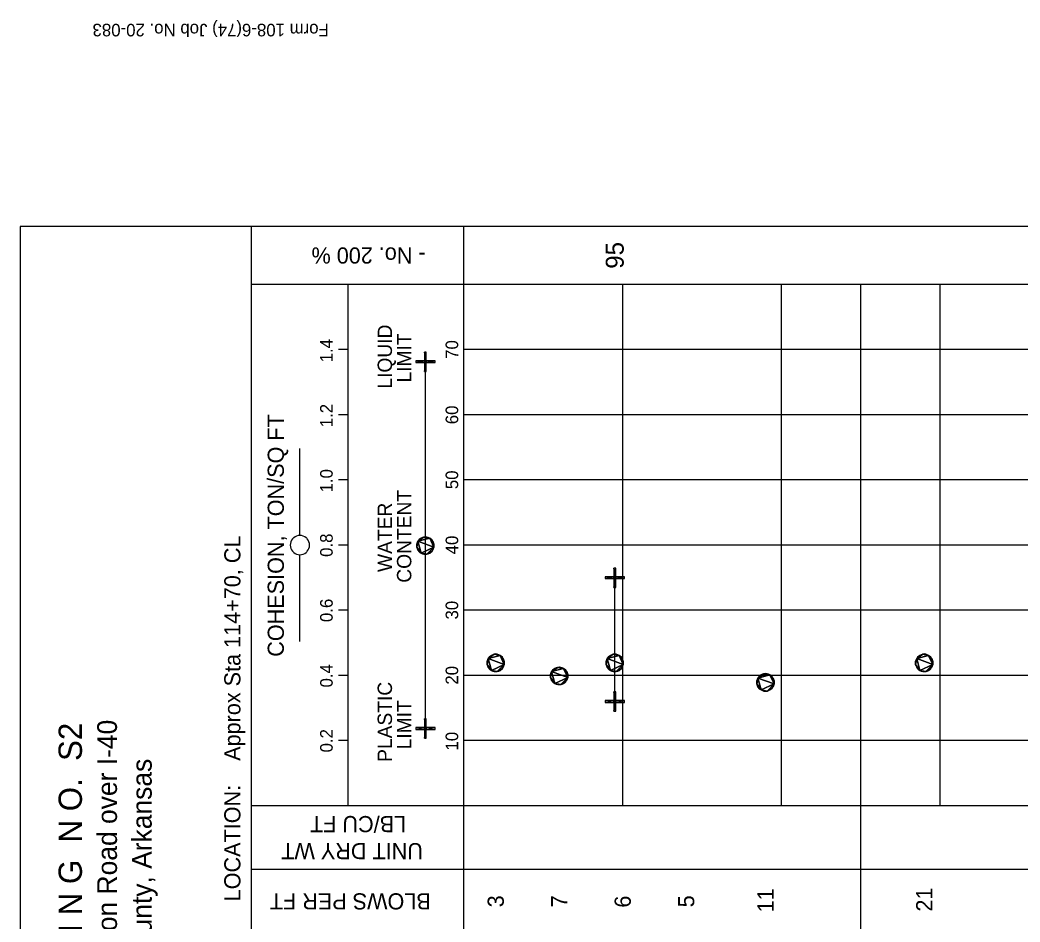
# Model space of a CAD drawing. Extents: x 1313964 to 1316843, y 2087046 to 2096619.
# Drawn here: x 1314075.31 to 1314106.81, y 2089839.67 to 2089868.08 of the extents above; entities that cross this region are included whole.
import ezdxf

# ---------------------------------------------------------------- set-up
doc = ezdxf.new("R2010")
doc.units = 0
doc.layers.add('B-Sub-Contour', color=7, linetype='Continuous')
doc.layers.add('Default', color=7, linetype='Continuous')

# ---------------------------------------------------------------- blocks, each defined once
blk = doc.blocks.new('POINT_DISPLAY')
at = {"layer": 'Default'}
blk.add_line((0, 0), (0, 0), dxfattribs=at)
blk = doc.blocks.new('DMK_101')
at = {"layer": 'Default'}
for points in [[(-14269.212, 2386.584), (-14476.476, 0), (-14269.212, -2386.584), (-14269.212, 2386.584)], [(-12638.532, 6858), (-13653.516, 4690.872), (-14269.212, 2386.584), (-12638.532, 6858)], [(-12638.532, 6858), (-14269.212, 2386.584), (-14269.212, -2386.584), (-12638.532, 6858)], [(-12638.532, 6858), (-14269.212, -2386.584), (-3147.06, -13508.736), (-12638.532, 6858)], [(-3147.06, 13511.784), (-7618.476, 11878.056), (-12638.532, 6858), (-3147.06, 13511.784)], [(6097.524, 11878.056), (-3147.06, 13511.784), (-12638.532, 6858), (6097.524, 11878.056)], [(-7618.476, 11878.056), (-11266.932, 8820.912), (-12638.532, 6858), (-7618.476, 11878.056)], [(-3147.06, -13508.736), (6097.524, 11878.056), (-12638.532, 6858), (-3147.06, -13508.736)], [(-7618.476, 11878.056), (-9578.34, 10506.456), (-11266.932, 8820.912), (-7618.476, 11878.056)], [(-9578.34, 10506.456), (-10456.164, 9698.736), (-11266.932, 8820.912), (-9578.34, 10506.456)], [(-3147.06, 13511.784), (-5451.348, 12893.04), (-7618.476, 11878.056), (-3147.06, 13511.784)], [(1626.108, 13511.784), (-760.476, 13712.952), (-3147.06, 13511.784), (1626.108, 13511.784)], [(6097.524, 11878.056), (1626.108, 13511.784), (-3147.06, 13511.784), (6097.524, 11878.056)], [(-3147.06, -13508.736), (11117.58, -6858), (6097.524, 11878.056), (-3147.06, -13508.736)], [(6097.524, 11878.056), (3930.396, 12893.04), (1626.108, 13511.784), (6097.524, 11878.056)], [(11117.58, 6858), (8060.436, 10506.456), (6097.524, 11878.056), (11117.58, 6858)], [(12751.308, 2386.584), (11117.58, 6858), (6097.524, 11878.056), (12751.308, 2386.584)], [(11117.58, -6858), (12751.308, 2386.584), (6097.524, 11878.056), (11117.58, -6858)], [(9745.98, 8820.912), (8938.26, 9698.736), (8060.436, 10506.456), (9745.98, 8820.912)], [(11117.58, 6858), (9745.98, 8820.912), (8060.436, 10506.456), (11117.58, 6858)], [(12751.308, 2386.584), (12132.564, 4690.872), (11117.58, 6858), (12751.308, 2386.584)], [(11117.58, -6858), (12751.308, -2386.584), (12751.308, 2386.584), (11117.58, -6858)], [(12751.308, -2386.584), (12952.476, 0), (12751.308, 2386.584), (12751.308, -2386.584)], [(-14269.212, -2386.584), (-13653.516, -4690.872), (-12638.532, -6858), (-14269.212, -2386.584)], [(-14269.212, -2386.584), (-12638.532, -6858), (-9578.34, -10506.456), (-14269.212, -2386.584)], [(-14269.212, -2386.584), (-9578.34, -10506.456), (-3147.06, -13508.736), (-14269.212, -2386.584)], [(-12638.532, -6858), (-11266.932, -8817.864), (-9578.34, -10506.456), (-12638.532, -6858)], [(-11266.932, -8817.864), (-10456.164, -9695.688), (-9578.34, -10506.456), (-11266.932, -8817.864)], [(-9578.34, -10506.456), (-7618.476, -11878.056), (-3147.06, -13508.736), (-9578.34, -10506.456)], [(-7618.476, -11878.056), (-5451.348, -12893.04), (-3147.06, -13508.736), (-7618.476, -11878.056)], [(-3147.06, -13508.736), (6097.524, -11878.056), (11117.58, -6858), (-3147.06, -13508.736)], [(-3147.06, -13508.736), (1626.108, -13508.736), (6097.524, -11878.056), (-3147.06, -13508.736)], [(-3147.06, -13508.736), (-760.476, -13716), (1626.108, -13508.736), (-3147.06, -13508.736)], [(1626.108, -13508.736), (3930.396, -12893.04), (6097.524, -11878.056), (1626.108, -13508.736)], [(6097.524, -11878.056), (8060.436, -10506.456), (11117.58, -6858), (6097.524, -11878.056)], [(8060.436, -10506.456), (9745.98, -8817.864), (11117.58, -6858), (8060.436, -10506.456)], [(8060.436, -10506.456), (8938.26, -9695.688), (9745.98, -8817.864), (8060.436, -10506.456)], [(11117.58, -6858), (12132.564, -4690.872), (12751.308, -2386.584), (11117.58, -6858)]]:
    blk.add_lwpolyline(points, close=True, dxfattribs=at)
blk.add_blockref('POINT_DISPLAY', (14479.524, 0), dxfattribs=at)
blk = doc.blocks.new('DMK_99')
at = {"layer": 'Default'}
for points in [[(-1524, -1524), (-1524, 1524), (-15240, 1524), (-1524, -1524)], [(-1524, -1524), (-15240, 1524), (-15240, -1524), (-1524, -1524)], [(1524, 1524), (1524, 15240), (-1524, 15240), (1524, 1524)], [(1524, 1524), (-1524, 15240), (-1524, 1524), (1524, 1524)], [(-1524, -1524), (1524, -1524), (1524, 1524), (-1524, -1524)], [(-1524, -1524), (1524, 1524), (-1524, 1524), (-1524, -1524)], [(1524, -1524), (15240, -1524), (15240, 1524), (1524, -1524)], [(1524, -1524), (15240, 1524), (1524, 1524), (1524, -1524)], [(-1524, -1524), (-1524, -15240), (1524, -15240), (-1524, -1524)], [(-1524, -1524), (1524, -15240), (1524, -1524), (-1524, -1524)]]:
    blk.add_lwpolyline(points, close=True, dxfattribs=at)
blk = doc.blocks.new('DMK_7')
at = {"layer": 'Default'}
blk.add_lwpolyline([(0, -15240), (2651.76, -15011.4), (5212.08, -14325.6), (7620, -13197.84), (9799.32, -11673.84), (10774.68, -10774.68), (11673.84, -9799.32), (13197.84, -7620), (14325.6, -5212.08), (15011.4, -2651.76), (15240, 0), (15011.4, 2651.76), (14325.6, 5212.08), (13197.84, 7620), (11673.84, 9799.32), (10774.68, 10774.68), (9799.32, 11673.84), (7620, 13197.84), (5212.08, 14325.6), (2651.76, 15011.4), (0, 15240), (-2651.76, 15011.4), (-5212.08, 14325.6), (-7620, 13197.84), (-9799.32, 11673.84), (-10774.68, 10774.68), (-11673.84, 9799.32), (-13197.84, 7620), (-14325.6, 5212.08), (-15011.4, 2651.76), (-15240, 0), (-15011.4, -2651.76), (-14325.6, -5212.08), (-13197.84, -7620), (-11673.84, -9799.32), (-10774.68, -10774.68), (-9799.32, -11673.84), (-7620, -13197.84), (-5212.08, -14325.6), (-2651.76, -15011.4), (0, -15240)], dxfattribs=at)

msp = doc.modelspace()

# ---------------------------------------------------------------- linework, layer by layer
at = {"layer": 'B-Sub-Contour'}
for points in [[(1314136.725, 2089818.705), (1314136.725, 2089861.576), (1314075.306, 2089861.576), (1314075.306, 2089818.705), (1314136.725, 2089818.705)], [(1314082.603, 2089818.705), (1314082.603, 2089861.576)], [(1314089.292, 2089818.705), (1314089.292, 2089861.576)], [(1314134.292, 2089859.752), (1314082.603, 2089859.752)], [(1314085.644, 2089859.752), (1314085.34, 2089859.752)], [(1314085.644, 2089843.333), (1314085.644, 2089859.752)], [(1314134.292, 2089859.752), (1314089.292, 2089859.752)], [(1314089.292, 2089843.333), (1314089.292, 2089859.752)], [(1314094.292, 2089843.333), (1314094.292, 2089859.752)], [(1314099.292, 2089843.333), (1314099.292, 2089859.752)], [(1314101.792, 2089839.319), (1314101.792, 2089859.752)], [(1314104.292, 2089843.333), (1314104.292, 2089859.752)], [(1314085.644, 2089857.7), (1314085.34, 2089857.7)], [(1314134.292, 2089857.7), (1314089.292, 2089857.7)], [(1314088.076, 2089845.765), (1314088.076, 2089857.319)], [(1314085.644, 2089855.647), (1314085.34, 2089855.647)], [(1314134.292, 2089855.647), (1314089.292, 2089855.647)], [(1314084.124, 2089851.846), (1314084.124, 2089854.583)], [(1314085.644, 2089853.595), (1314085.34, 2089853.595)], [(1314134.292, 2089853.595), (1314089.292, 2089853.595)], [(1314085.644, 2089851.542), (1314085.34, 2089851.542)], [(1314134.292, 2089851.542), (1314089.292, 2089851.542)], [(1314084.124, 2089848.502), (1314084.124, 2089851.238)], [(1314094.042, 2089846.617), (1314094.042, 2089850.516)], [(1314094.042, 2089846.617), (1314094.042, 2089850.516)], [(1314085.644, 2089849.49), (1314085.34, 2089849.49)], [(1314134.292, 2089849.49), (1314089.292, 2089849.49)], [(1314085.644, 2089847.438), (1314085.34, 2089847.438)], [(1314134.292, 2089847.438), (1314089.292, 2089847.438)], [(1314085.644, 2089845.385), (1314085.34, 2089845.385)], [(1314134.292, 2089845.385), (1314089.292, 2089845.385)], [(1314134.292, 2089843.333), (1314082.603, 2089843.333)], [(1314085.644, 2089843.333), (1314085.34, 2089843.333)], [(1314134.292, 2089843.333), (1314089.292, 2089843.333)], [(1314134.292, 2089841.326), (1314082.603, 2089841.326)]]:
    msp.add_lwpolyline(points, dxfattribs=at)

# ---------------------------------------------------------------- block references
at = {"layer": 'B-Sub-Contour', "xscale": 1.9951013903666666e-05, "yscale": 1.9951013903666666e-05, "rotation": 90}
for name, p in [('DMK_99', (1314088.076, 2089857.319)), ('DMK_7', (1314084.124, 2089851.542)), ('DMK_101', (1314088.076, 2089851.542)), ('DMK_99', (1314094.042, 2089850.516)), ('DMK_99', (1314094.042, 2089850.516)), ('DMK_101', (1314090.292, 2089847.848)), ('DMK_101', (1314090.292, 2089847.848)), ('DMK_101', (1314094.042, 2089847.848)), ('DMK_101', (1314094.042, 2089847.848)), ('DMK_101', (1314103.792, 2089847.848)), ('DMK_101', (1314103.792, 2089847.848)), ('DMK_101', (1314092.292, 2089847.438)), ('DMK_101', (1314092.292, 2089847.438)), ('DMK_101', (1314098.792, 2089847.232)), ('DMK_101', (1314098.792, 2089847.232)), ('DMK_99', (1314094.042, 2089846.617)), ('DMK_99', (1314094.042, 2089846.617)), ('DMK_99', (1314088.076, 2089845.765))]:
    msp.add_blockref(name, p, dxfattribs=at)

# ---------------------------------------------------------------- texts
at = {"layer": 'B-Sub-Contour'}
for s, height, rotation, p in [('Form 108-6(74) Job No. 20-083', 0.39588, 180, (1314085.036, 2089867.961)), ('95', 0.5655, 90, (1314094.325, 2089860.247)), ('- No. 200 %', 0.50899, 180, (1314088.084, 2089860.919)), ('LIQUID', 0.4524, 90, (1314087.025, 2089856.471)), ('LIMIT', 0.4524, 90, (1314087.634, 2089856.664)), ('1.4', 0.3959, 90, (1314085.157, 2089857.298)), ('70', 0.3959, 90, (1314089.11, 2089857.408)), ('1.2', 0.3959, 90, (1314085.157, 2089855.253)), ('COHESION, TON/SQ FT', 0.50899, 90, (1314083.618, 2089848.026)), ('60', 0.3959, 90, (1314089.11, 2089855.349)), ('1.0', 0.3959, 90, (1314085.157, 2089853.201)), ('50', 0.3959, 90, (1314089.11, 2089853.304)), ('CONTENT', 0.4524, 90, (1314087.634, 2089850.358)), ('WATER', 0.4524, 90, (1314087.025, 2089850.694)), ('0.8', 0.3959, 90, (1314085.157, 2089851.171)), ('LOCATION:    Approx Sta 114+70, CL', 0.50899, 90, (1314082.25, 2089840.323)), ('40', 0.3959, 90, (1314089.11, 2089851.251)), ('0.6', 0.3959, 90, (1314085.157, 2089849.118)), ('30', 0.3959, 90, (1314089.11, 2089849.199)), ('0.4', 0.3959, 90, (1314085.157, 2089847.058)), ('20', 0.3959, 90, (1314089.11, 2089847.147)), ('PLASTIC', 0.4524, 90, (1314087.025, 2089844.715)), ('LIMIT', 0.4524, 90, (1314087.634, 2089845.11)), ('L O G  O F  B O R I N G  N O.  S2', 0.7352, 90, (1314077.257, 2089831.033)), ('061610 - Remington Road over I-40', 0.62209, 90, (1314078.361, 2089832.77)), ('0.2', 0.3959, 90, (1314085.157, 2089845.013)), ('10', 0.3959, 90, (1314089.11, 2089845.072)), ('Lonoke County, Arkansas', 0.62209, 90, (1314079.455, 2089835.288)), ('LB/CU FT', 0.509, 180, (1314087.47, 2089843.01)), ('UNIT DRY WT', 0.50899, 180, (1314087.999, 2089842.158)), ('BLOWS PER FT', 0.50899, 180, (1314088.245, 2089840.577)), ('11', 0.509, 90, (1314099.047, 2089839.973)), ('21', 0.509, 90, (1314104.047, 2089840.001)), ('3', 0.509, 90, (1314090.547, 2089840.134)), ('7', 0.509, 90, (1314092.547, 2089840.134)), ('6', 0.509, 90, (1314094.547, 2089840.124)), ('5', 0.509, 90, (1314096.547, 2089840.134))]:
    msp.add_text(s, height=height, rotation=rotation, dxfattribs=at).set_placement(p)

doc.saveas('drawing.dxf')
